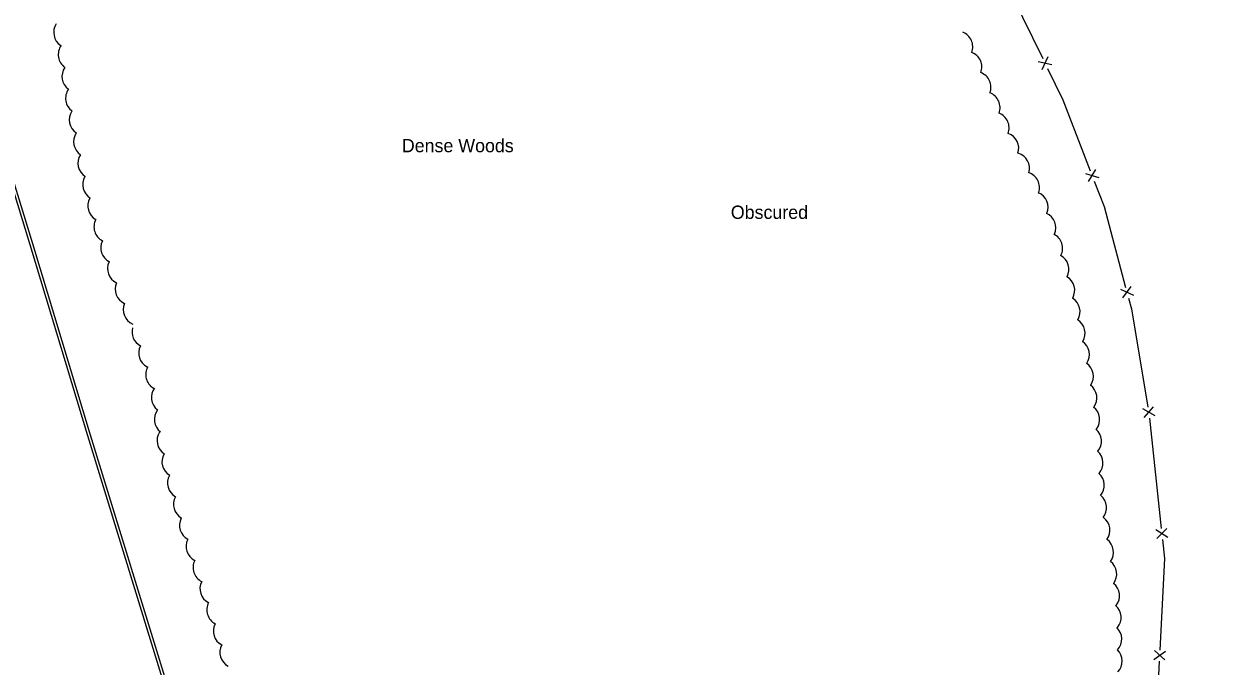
# Model space of a CAD drawing. Extents: x 2402803 to 2427059, y 6985292 to 6997652.
# Drawn here: x 2410493.1 to 2410922.2, y 6994386.2 to 6994617.7 of the extents above; entities that cross this region are included whole.
import ezdxf

# ---------------------------------------------------------------- set-up
doc = ezdxf.new("R2010")
doc.units = 0
for name, color, linetype in [('p_road - paved curb', 7, 'Continuous'), ('p_structure fence', 7, 'Continuous'), ('p_veg woods', 7, 'Continuous')]:
    doc.layers.add(name, color=color, linetype=linetype)

msp = doc.modelspace()

# ---------------------------------------------------------------- linework, layer by layer
at = {"layer": 'p_road - paved curb'}
for points in [[(2410306.58, 6995159.06), (2410317.51, 6995123.26), (2410332.04, 6995073.73), (2410357.55, 6994987.95), (2410377.82, 6994919.64), (2410401.66, 6994846.48), (2410427.86, 6994761.85), (2410450.65, 6994684.83), (2410472.26, 6994613.27), (2410495.25, 6994538.26), (2410516.15, 6994469.31), (2410545.24, 6994374.36), (2410567.49, 6994301.28), (2410587.33, 6994233.52), (2410608.02, 6994165.42), (2410640.02, 6994062.88), (2410651.18, 6994026.44), (2410653.2, 6994024.73), (2410656.65, 6994024.76)], [(2410322.54, 6995109.68), (2410333, 6995074.01), (2410358.51, 6994988.23), (2410378.77, 6994919.94), (2410402.61, 6994846.78), (2410428.82, 6994762.14), (2410451.61, 6994685.12), (2410473.22, 6994613.56), (2410496.21, 6994538.55), (2410517.11, 6994469.6), (2410546.2, 6994374.65), (2410568.45, 6994301.57), (2410584.93, 6994245.29)]]:
    msp.add_lwpolyline(points, dxfattribs=at)
at = {"layer": 'p_structure fence'}
for p, q in [((2410860.11, 6994601.29), (2410862.3, 6994605.92)), ((2410858.71, 6994604.17), (2410863.7, 6994603.04)), ((2410875.76, 6994563.85), (2410880.64, 6994562.31)), ((2410876.91, 6994560.86), (2410879.49, 6994565.29)), ((2410888.4, 6994522.06), (2410893.08, 6994520)), ((2410889.22, 6994518.97), (2410892.26, 6994523.09)), ((2410896.35, 6994479.07), (2410900.82, 6994476.58)), ((2410896.88, 6994475.91), (2410900.29, 6994479.73)), ((2410898.81, 6994475.64), (2410903.09, 6994435.87)), ((2410901.15, 6994435.46), (2410905.47, 6994432.71)), ((2410901.49, 6994432.28), (2410905.13, 6994435.89)), ((2410900.44, 6994388.69), (2410904.59, 6994391.68)), ((2410900.6, 6994391.89), (2410904.43, 6994388.49))]:
    msp.add_line(p, q, dxfattribs=at)
for points in [[(2410842.05, 6994640.73), (2410849.38, 6994627.83), (2410860.39, 6994605.21)], [(2410862.14, 6994601.61), (2410867.62, 6994590.35), (2410877.52, 6994564.75)], [(2410878.96, 6994561.02), (2410882.51, 6994551.85), (2410890.25, 6994522.76)], [(2410891.28, 6994518.9), (2410892.3, 6994515.05), (2410898.26, 6994479.59)], [(2410903.52, 6994431.9), (2410904.25, 6994425.09), (2410902.58, 6994391.99)], [(2410902.37, 6994387.99), (2410901.48, 6994370.33), (2410922.16, 6994362.11)]]:
    msp.add_lwpolyline(points, dxfattribs=at)
at = {"layer": 'p_veg woods'}
for centre, start, end in [((2410509.55, 6994614.65), 146.7903, 236.7903), ((2410829.5, 6994609.45), 339.1769, 69.1769), ((2410511.19, 6994606.68), 144.8655, 234.8655), ((2410832.78, 6994602.15), 339.1769, 69.1769), ((2410512.55, 6994598.77), 144.5035, 234.5035), ((2410836.05, 6994594.86), 339.1769, 69.1769), ((2410513.84, 6994590.9), 144.9422, 234.9422), ((2410839.33, 6994587.56), 339.1769, 69.1769), ((2410515.19, 6994583.1), 146.1224, 236.1224), ((2410842.6, 6994580.26), 339.1769, 69.1769), ((2410516.72, 6994575.28), 146.5695, 236.5695), ((2410846.06, 6994572.91), 340.9671, 70.9671), ((2410518.29, 6994567.52), 147.7138, 237.7138), ((2410849.93, 6994565.72), 343.2457, 73.2457), ((2410520.01, 6994559.79), 148.9518, 238.9518), ((2410853.57, 6994558.7), 341.9711, 71.9711), ((2410521.86, 6994552.17), 151.1569, 241.1569), ((2410856.65, 6994551.61), 338.1541, 68.1541), ((2410524.07, 6994544.59), 152.6926, 242.6926), ((2410859.45, 6994544.27), 336.0207, 66.0207), ((2410861.88, 6994536.83), 333.5139, 63.5139), ((2410526.52, 6994537), 153.1159, 243.1159), ((2410864.14, 6994529.27), 331.8997, 61.8997), ((2410528.96, 6994529.5), 154.745, 244.745), ((2410531.7, 6994522.12), 156.5014, 246.5014), ((2410866.25, 6994521.65), 330.6367, 60.6367), ((2410534.64, 6994514.68), 156.5014, 246.5014), ((2410868.19, 6994513.98), 329.2925, 59.2925), ((2410537.77, 6994506.73), 164.8749, 242.4717), ((2410869.97, 6994506.27), 328.0489, 58.0489), ((2410871.53, 6994498.52), 326.6153, 56.6153), ((2410540.17, 6994499.1), 152.4717, 242.4717), ((2410542.73, 6994491.29), 149.414, 239.414), ((2410872.98, 6994490.72), 325.677, 55.677), ((2410544.75, 6994483.07), 142.8108, 232.8108), ((2410874.24, 6994482.92), 324.2539, 54.2539), ((2410545.83, 6994475.13), 142.6068, 232.6068), ((2410875.24, 6994475.13), 322.2403, 52.2403), ((2410546.82, 6994467.51), 147.0444, 237.0444), ((2410875.9, 6994467.34), 319.5964, 49.5964), ((2410548.57, 6994459.91), 149.7918, 239.7918), ((2410876.42, 6994459.41), 318.8676, 48.8676), ((2410876.91, 6994451.44), 318.6553, 48.6553), ((2410550.59, 6994452.23), 150.5995, 240.5995), ((2410552.74, 6994444.57), 151.0592, 241.0592), ((2410877.74, 6994443.34), 320.7085, 50.7085), ((2410554.91, 6994436.98), 152.4327, 242.4327), ((2410878.91, 6994435.27), 322.9341, 52.9341), ((2410557.28, 6994429.39), 153.1356, 243.1356), ((2410880.21, 6994427.3), 324.0236, 54.0236), ((2410559.77, 6994421.79), 153.182, 243.182), ((2410881.4, 6994419.44), 323.4003, 53.4003), ((2410562.27, 6994414.17), 152.8484, 242.8484), ((2410882.4, 6994411.59), 322.1884, 52.1884), ((2410564.72, 6994406.53), 152.3871, 242.3871), ((2410882.97, 6994403.81), 319.399, 49.399), ((2410567.1, 6994398.87), 152.0631, 242.0631), ((2410883.22, 6994395.99), 317.0368, 47.0368), ((2410569.45, 6994391.21), 151.8612, 241.8612), ((2410883.35, 6994388.07), 315.9807, 45.9807)]:
    msp.add_arc(centre, 5.65, start, end, dxfattribs=at)

# ---------------------------------------------------------------- texts
for s, p in [('Dense Woods', (2410629.39, 6994571.45)), ('Obscured', (2410747.95, 6994547.43))]:
    msp.add_text(s, height=4.8, dxfattribs=at).set_placement(p)

doc.saveas('drawing.dxf')
